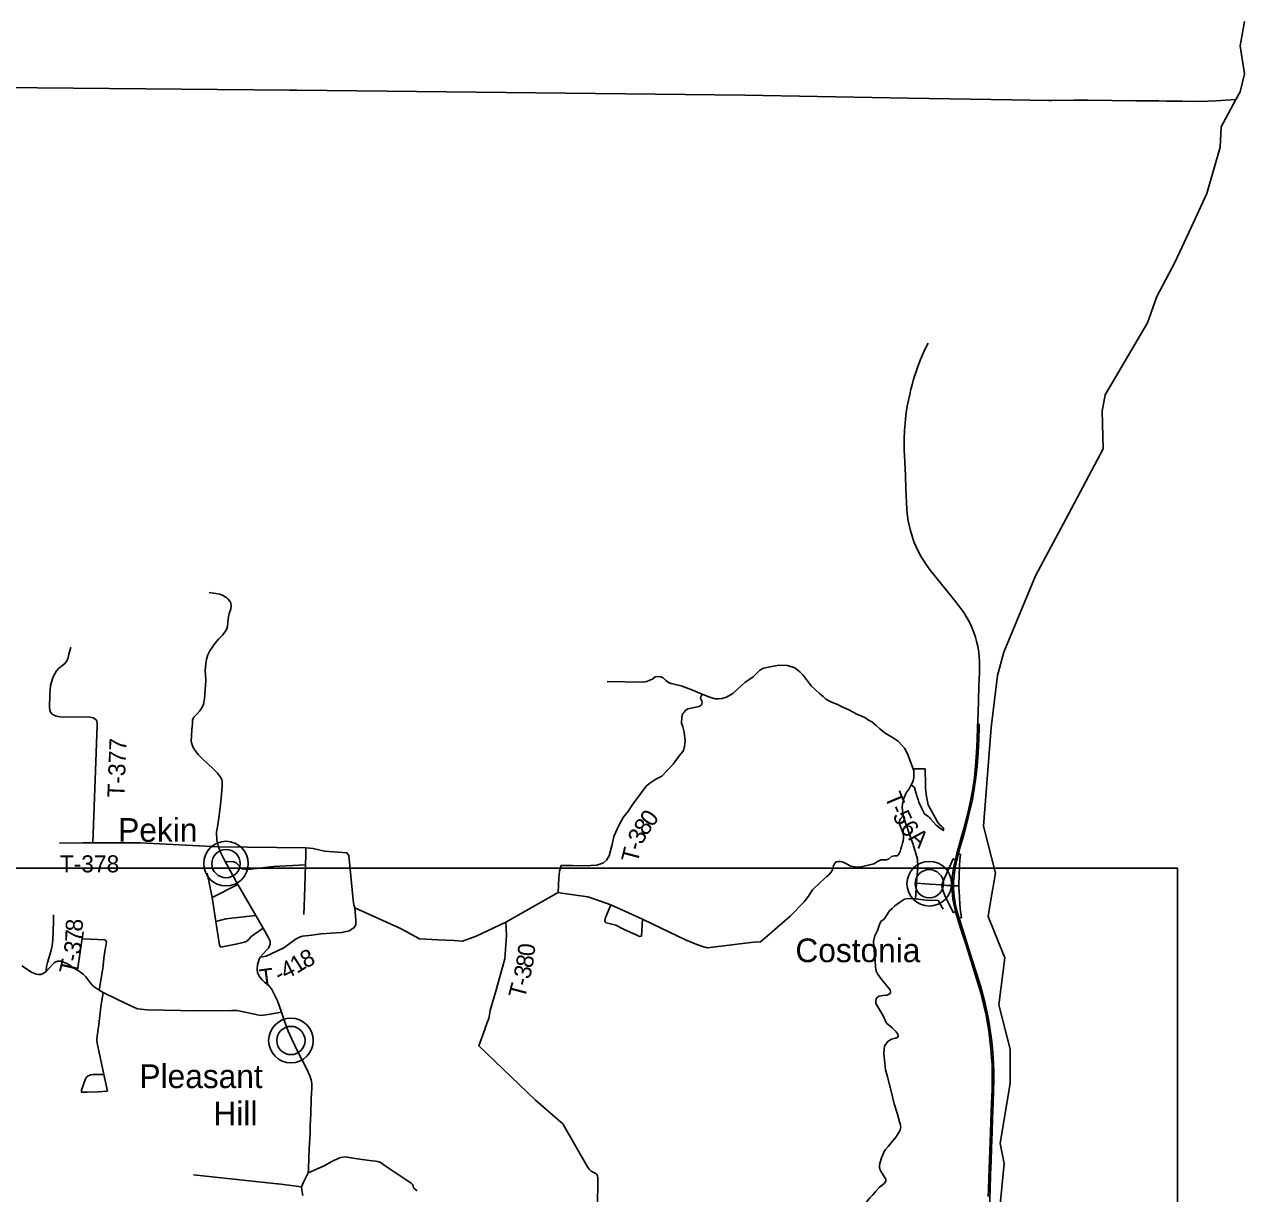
# Model space of a CAD drawing. Extents: x 2402298 to 2498138, y 789485 to 950881.
# Drawn here: x 2476534 to 2498020, y 883995 to 904591 of the extents above; entities that cross this region are included whole.
import ezdxf

# ---------------------------------------------------------------- set-up
doc = ezdxf.new("R2010")
doc.units = 0
for name, color, linetype in [('GM_X_County', 7, 'Continuous'), ('GM_X_County_Road', 7, 'Continuous'), ('GM_X_Interchange_Ramps', 7, 'Continuous'), ('GM_X_State_Route', 7, 'Continuous'), ('GM_X_Township', 7, 'Continuous'), ('GM_X_Township_Road', 7, 'Continuous'), ('GM_X_Township_Road_Text', 7, 'Continuous'), ('GM_X_Unincorporated', 7, 'Continuous'), ('GM_X_Unincorporated_Text', 7, 'Continuous'), ('SH_Text', 7, 'Continuous')]:
    doc.layers.add(name, color=color, linetype=linetype)

msp = doc.modelspace()

# ---------------------------------------------------------------- linework, layer by layer
at = {"layer": 'GM_X_County'}
msp.add_lwpolyline([(2498018, 904641), (2497940, 904212), (2498020, 903722), (2497939, 903401), (2497868, 903270), (2497606, 902788), (2497589, 902427), (2497357, 901615), (2497080, 901013), (2496789, 900399), (2496476, 899798), (2496307, 899333), (2495566, 898065), (2495514, 897781), (2495530, 897113), (2494920, 895961), (2494340, 894878), (2493781, 893531), (2493667, 893121), (2493560, 892205), (2493420, 890468), (2493631, 889637), (2493547, 889137), (2493504, 888879), (2493797, 888149), (2493690, 887319), (2493891, 886541), (2493889, 885939), (2493714, 884880), (2493786, 884527), (2493696, 883623)], dxfattribs=at)
at = {"layer": 'GM_X_County_Road'}
for points in [[(2486798, 893016), (2487422, 893005), (2487492, 893018), (2487598, 893066), (2487643, 893096), (2487687, 893104), (2487741, 893096), (2487782, 893078), (2487829, 893032), (2487874, 893001), (2487921, 892978), (2488096, 892942), (2488286, 892872), (2488469, 892792), (2488566, 892753), (2488637, 892726), (2488695, 892709), (2488753, 892712), (2488820, 892716), (2488896, 892741), (2489008, 892802), (2489222, 893001), (2489290, 893047), (2489364, 893101), (2489481, 893218), (2489551, 893252), (2489639, 893270), (2489753, 893295), (2489817, 893305), (2489972, 893297), (2490098, 893255), (2490187, 893188), (2490246, 893127), (2490386, 892942), (2490465, 892869), (2490534, 892805), (2490597, 892751), (2490648, 892707), (2490744, 892653), (2490841, 892615), (2490948, 892564), (2491065, 892510), (2491193, 892442), (2491335, 892381), (2491400, 892337), (2491455, 892306), (2491534, 892243), (2491594, 892180), (2491693, 892106), (2491831, 892023), (2491917, 891964), (2491980, 891903), (2492029, 891842), (2492085, 891742), (2492184, 891476), (2492194, 891445), (2492197, 891409), (2492197, 891399)], [(2492197, 891399), (2492197, 891366), (2492194, 891331), (2492188, 891291), (2492175, 891246), (2492150, 891193), (2492113, 891127), (2492063, 891057), (2492011, 890941), (2491994, 890858), (2491987, 890804), (2492007, 890649), (2492112, 890339), (2492185, 890144), (2492260, 889884), (2492267, 889753), (2492245, 889462), (2492472, 889446), (2492691, 889432), (2492779, 889425), (2492867, 889420), (2492896, 889418), (2492988, 889414)], [(2476487, 888005), (2476659, 887898), (2476700, 887879), (2476743, 887861), (2476780, 887854), (2476823, 887856), (2476866, 887873), (2476916, 887908), (2476977, 887974), (2477031, 888032), (2477056, 888059), (2477085, 888077), (2477120, 888087), (2477148, 888090), (2477184, 888089), (2477225, 888073), (2477282, 888046), (2477321, 888023), (2477393, 887975), (2477468, 887932), (2477519, 887896), (2477570, 887861), (2477616, 887811), (2477685, 887722), (2477747, 887647), (2477853, 887576), (2477921, 887540), (2478149, 887425), (2478294, 887355), (2478418, 887297), (2478524, 887251), (2478687, 887230), (2479584, 887214), (2480181, 887220), (2480281, 887218), (2480475, 887177), (2480586, 887154), (2480690, 887134), (2480828, 887151), (2481063, 887191)]]:
    msp.add_lwpolyline(points, dxfattribs=at)
at = {"layer": 'GM_X_Interchange_Ramps'}
for points in [[(2492988, 889414), (2492987, 889450), (2492992, 889587), (2492998, 889774), (2493008, 889870), (2493020, 889971), (2492982, 889980)], [(2492928, 889879), (2492889, 889894), (2492820, 889736), (2492737, 889554), (2492715, 889507), (2492701, 889463), (2492691, 889432)], [(2492691, 889432), (2492691, 889413), (2492695, 889387), (2492713, 889326), (2492748, 889228), (2492786, 889151), (2492824, 889076), (2492868, 888989), (2492888, 888945), (2492931, 888958)], [(2492992, 888850), (2493035, 888858), (2493020, 888968), (2493008, 889081), (2492998, 889225), (2492988, 889393), (2492988, 889414)]]:
    msp.add_lwpolyline(points, dxfattribs=at)
at = {"layer": 'GM_X_State_Route'}
for points in [[(2493506, 883946), (2493510, 884073), (2493518, 884269), (2493523, 884430), (2493529, 884590), (2493534, 884751), (2493540, 884910), (2493546, 885071), (2493553, 885271), (2493559, 885427), (2493564, 885588), (2493569, 885707), (2493573, 885827), (2493576, 885988), (2493575, 886148), (2493572, 886268), (2493565, 886388), (2493553, 886546), (2493536, 886705), (2493514, 886864), (2493488, 887024), (2493461, 887174), (2493425, 887334), (2493399, 887434), (2493374, 887529), (2493330, 887682), (2493271, 887872), (2493198, 888105), (2493114, 888369), (2493030, 888636), (2492965, 888842), (2492931, 888958), (2492915, 889026), (2492899, 889097), (2492885, 889179), (2492875, 889259), (2492867, 889354), (2492867, 889420), (2492869, 889494), (2492873, 889567), (2492882, 889647), (2492901, 889763), (2492928, 889879), (2492954, 889985), (2492987, 890110), (2493036, 890287), (2493068, 890401), (2493110, 890557), (2493157, 890749), (2493199, 890944), (2493232, 891127), (2493261, 891326), (2493283, 891525), (2493301, 891763), (2493311, 892001), (2493318, 892212), (2493326, 892454), (2493333, 892690), (2493342, 892931), (2493350, 893171), (2493351, 893281), (2493349, 893370), (2493345, 893450), (2493337, 893528), (2493320, 893640), (2493301, 893724), (2493279, 893800), (2493252, 893879), (2493211, 893983), (2493174, 894061), (2493119, 894159), (2493074, 894231), (2493006, 894326), (2492907, 894453), (2492733, 894667), (2492606, 894823), (2492481, 894980), (2492412, 895075), (2492369, 895140), (2492325, 895213), (2492272, 895313), (2492237, 895387), (2492204, 895464), (2492177, 895538), (2492152, 895616), (2492131, 895691), (2492113, 895770), (2492098, 895848), (2492086, 895928), (2492074, 896047), (2492067, 896167), (2492056, 896407), (2492046, 896647), (2492036, 896885), (2492027, 897097), (2492026, 897150), (2492027, 897287), (2492033, 897443), (2492042, 897560), (2492050, 897645), (2492063, 897756), (2492080, 897866), (2492099, 897973), (2492122, 898073), (2492143, 898164), (2492164, 898243), (2492186, 898321), (2492209, 898396), (2492234, 898472), (2492260, 898549), (2492303, 898659), (2492343, 898756), (2492396, 898876), (2492446, 898977)], [(2479952, 890575), (2479962, 890658), (2479986, 890848), (2480003, 891027), (2480016, 891181), (2480016, 891235), (2480011, 891290), (2479985, 891333), (2479933, 891401), (2479857, 891477), (2479761, 891563), (2479676, 891650), (2479592, 891730), (2479534, 891808), (2479502, 891868), (2479473, 891960), (2479479, 892060), (2479483, 892165), (2479491, 892268), (2479492, 892333), (2479520, 892388), (2479574, 892445), (2479625, 892502), (2479661, 892552), (2479688, 892619), (2479707, 892710), (2479724, 892949), (2479728, 893042), (2479721, 893130), (2479719, 893216), (2479728, 893328), (2479739, 893412), (2479764, 893486), (2479797, 893554), (2479838, 893617), (2479889, 893683), (2479953, 893761), (2480023, 893833), (2480063, 893883), (2480090, 893932), (2480108, 893985), (2480119, 894056), (2480129, 894160), (2480137, 894206), (2480167, 894299), (2480177, 894351), (2480170, 894398), (2480154, 894433), (2480119, 894471), (2480097, 894490), (2480077, 894502), (2480031, 894530), (2479969, 894553), (2479904, 894565), (2479865, 894571), (2479788, 894585)], [(2493529, 883788), (2493539, 884061), (2493548, 884331), (2493556, 884565), (2493564, 884801), (2493575, 885078), (2493583, 885319), (2493593, 885600), (2493600, 885798), (2493605, 885999), (2493603, 886152), (2493599, 886279), (2493593, 886398), (2493580, 886556), (2493563, 886715), (2493541, 886874), (2493515, 887031), (2493487, 887182), (2493452, 887345), (2493424, 887453), (2493389, 887589), (2493368, 887655), (2493298, 887880), (2493225, 888112), (2493141, 888376), (2493057, 888644), (2492992, 888850), (2492958, 888965), (2492926, 889106), (2492904, 889242), (2492896, 889353), (2492896, 889418), (2492896, 889489), (2492899, 889536), (2492910, 889654), (2492931, 889770), (2492952, 889870), (2492982, 889980), (2493020, 890119), (2493074, 890315), (2493136, 890545), (2493184, 890741), (2493227, 890940), (2493260, 891127), (2493289, 891326), (2493311, 891525), (2493329, 891763), (2493339, 892002), (2493346, 892213), (2493348, 892271)], [(2481439, 883960), (2481419, 884057), (2481415, 884113), (2481450, 884194), (2481491, 884276), (2481528, 884361), (2481538, 884427), (2481542, 884625), (2481550, 884777), (2481564, 885074), (2481568, 885189), (2481575, 885408), (2481584, 885662), (2481594, 885860), (2481594, 885934), (2481583, 886001), (2481561, 886070), (2481508, 886190), (2481351, 886494), (2481238, 886730), (2481178, 886856), (2481115, 887035), (2481063, 887191), (2480992, 887389), (2480928, 887518), (2480885, 887600), (2480828, 887671), (2480763, 887717), (2480720, 887761), (2480678, 887808), (2480655, 887849), (2480637, 887891), (2480631, 887942), (2480637, 888025), (2480665, 888122), (2480683, 888163), (2480741, 888221), (2480794, 888279), (2480839, 888326), (2480863, 888389), (2480861, 888441), (2480829, 888513), (2480736, 888671), (2480610, 888895), (2480292, 889438), (2480071, 889845), (2479987, 890008), (2479953, 890106), (2479920, 890221), (2479919, 890361), (2479942, 890493), (2479952, 890575)]]:
    msp.add_lwpolyline(points, dxfattribs=at)
at = {"layer": 'GM_X_Township'}
msp.add_lwpolyline([(2471955, 903500), (2476767, 903474), (2481204, 903434), (2481335, 903433), (2489222, 903345), (2492100, 903289), (2493922, 903261), (2494572, 903249), (2494576, 903250), (2494618, 903250), (2495010, 903254), (2495137, 903258), (2495262, 903257), (2496107, 903247), (2496512, 903242), (2496642, 903240), (2496922, 903237), (2497230, 903236), (2497515, 903245), (2497868, 903270), (2497606, 902788), (2497589, 902427), (2497357, 901615), (2497080, 901013), (2496789, 900399), (2496476, 899798), (2496307, 899333), (2495566, 898065), (2495514, 897781), (2495530, 897113), (2494920, 895961), (2494340, 894878), (2493781, 893531), (2493667, 893121), (2493560, 892205), (2493420, 890468), (2493631, 889637), (2493547, 889137), (2493504, 888879), (2493797, 888149), (2493690, 887319), (2493891, 886541), (2493889, 885939), (2493714, 884880), (2493786, 884527), (2493696, 883623)], dxfattribs=at)
at = {"layer": 'GM_X_Township_Road'}
for p, q in [((2479839, 889210), (2480292, 889438)), ((2485012, 888779), (2485930, 889301)), ((2492227, 889188), (2492245, 889462)), ((2477468, 887932), (2477548, 888452)), ((2477552, 888483), (2477958, 888464)), ((2479509, 884323), (2480982, 884169))]:
    msp.add_line(p, q, dxfattribs=at)
for points in [[(2477741, 890174), (2477767, 890972), (2477794, 891605), (2477818, 892246), (2477815, 892286), (2477807, 892317), (2477795, 892340), (2477775, 892361), (2477744, 892377), (2477692, 892385), (2477164, 892394), (2477128, 892400), (2477081, 892409), (2477051, 892421), (2477018, 892446), (2476995, 892477), (2476982, 892514), (2476977, 892563), (2476984, 892784), (2476996, 892944), (2477005, 892986), (2477043, 893100), (2477067, 893153), (2477101, 893202), (2477141, 893249), (2477206, 893296), (2477251, 893340), (2477279, 893378), (2477305, 893433), (2477318, 893500), (2477349, 893623)], [(2488125, 891781), (2488141, 891801), (2488160, 891876), (2488168, 891970), (2488152, 892126), (2488129, 892219), (2488102, 892285), (2488110, 892387), (2488115, 892420), (2488128, 892450), (2488148, 892471), (2488172, 892506), (2488215, 892535), (2488414, 892574), (2488449, 892599), (2488465, 892621), (2488470, 892644), (2488463, 892669), (2488450, 892700), (2488440, 892722), (2488442, 892746), (2488469, 892792)], [(2485930, 889301), (2485947, 889560), (2485959, 889674), (2485971, 889738), (2485985, 889777), (2486187, 889775), (2486381, 889771), (2486509, 889772), (2486616, 889780), (2486731, 889822), (2486785, 889870), (2486828, 889943), (2486881, 890144), (2486912, 890287), (2486993, 890467), (2487080, 890622), (2487171, 890740), (2487250, 890858), (2487401, 891063), (2487484, 891173), (2487546, 891226), (2487655, 891297), (2487757, 891350), (2487959, 891559), (2488065, 891707), (2488125, 891781)], [(2492642, 890447), (2492715, 890390), (2492720, 890413), (2492718, 890424), (2492709, 890440), (2492689, 890460), (2492657, 890483), (2492617, 890534), (2492445, 890845), (2492417, 890993), (2492398, 891136), (2492403, 891198), (2492392, 891476), (2492184, 891476)], [(2492150, 891193), (2492205, 891150), (2492232, 891062), (2492252, 890985), (2492269, 890940), (2492282, 890889), (2492333, 890788), (2492354, 890741), (2492369, 890710), (2492379, 890686), (2492400, 890672), (2492444, 890644), (2492460, 890632), (2492476, 890614), (2492490, 890598), (2492591, 890487), (2492642, 890447)], [(2491981, 890112), (2491985, 890122), (2491997, 890166), (2492007, 890208), (2492015, 890256), (2492016, 890305), (2492008, 890340), (2491986, 890402), (2491957, 890474), (2491939, 890534), (2491942, 890563), (2491958, 890598), (2492007, 890649)], [(2477152, 890170), (2477561, 890174), (2477646, 890174), (2477741, 890174), (2478163, 890175), (2478574, 890175), (2479953, 890106)], [(2479953, 890106), (2481490, 890084), (2481616, 890076), (2481819, 890030), (2482213, 889999), (2482248, 889953), (2482322, 889167), (2482335, 889080), (2482352, 889029)], [(2481457, 888913), (2481463, 889061), (2481465, 889211), (2481485, 889789), (2481490, 889949), (2481490, 890084)], [(2490283, 889161), (2490339, 889233), (2490413, 889348), (2490544, 889474), (2490613, 889535), (2490663, 889582), (2490699, 889612), (2490736, 889651), (2490762, 889699), (2490780, 889771), (2490791, 889801), (2490808, 889824), (2490835, 889840), (2490871, 889848), (2490901, 889848), (2490932, 889842), (2490964, 889827), (2491010, 889802), (2491088, 889766), (2491162, 889753), (2491211, 889748), (2491245, 889748), (2491491, 889803), (2491578, 889859), (2491618, 889872), (2491706, 889874), (2491750, 889886), (2491802, 889932), (2491847, 889945), (2491898, 889948), (2491925, 889964), (2491938, 889985), (2491954, 890024), (2491964, 890071), (2491981, 890112)], [(2480071, 889845), (2480224, 889841), (2480262, 889819), (2480361, 889718), (2480468, 889705), (2480923, 889755), (2481485, 889789)], [(2479992, 888336), (2479968, 888370), (2479903, 888791), (2479839, 889210), (2479755, 889638)], [(2485930, 889301), (2485997, 889287), (2486244, 889255), (2486455, 889224), (2486677, 889145), (2486861, 889080), (2487416, 888829), (2487597, 888741), (2488174, 888465), (2488372, 888384), (2488494, 888343), (2488524, 888335)], [(2486861, 889080), (2486758, 888841), (2486752, 888801), (2486761, 888783), (2486775, 888764), (2486829, 888753), (2486951, 888722), (2487085, 888653), (2487319, 888546), (2487363, 888523), (2487399, 888531), (2487416, 888829)], [(2488524, 888335), (2488560, 888326), (2489372, 888427), (2489495, 888431), (2489662, 888570), (2490016, 888882), (2490260, 889131), (2490283, 889161)], [(2491861, 889062), (2491943, 889126), (2491993, 889158), (2492029, 889179), (2492096, 889191), (2492227, 889188), (2492413, 889167), (2492621, 889158), (2492631, 889153), (2492655, 889106), (2492714, 889004)], [(2476916, 887908), (2476925, 887997), (2476942, 888065), (2476964, 888143), (2477004, 888282), (2477020, 888362), (2477034, 888471), (2477040, 888620), (2477044, 888786), (2477049, 888905)], [(2479903, 888791), (2480083, 888837), (2480610, 888895)], [(2480683, 888163), (2480729, 888164), (2480793, 888179), (2480993, 888272), (2481102, 888327), (2481214, 888405), (2481321, 888481), (2481376, 888511), (2481430, 888530), (2481597, 888550), (2481757, 888569), (2481930, 888580), (2482126, 888597), (2482253, 888625), (2482336, 888675), (2482369, 888731), (2482370, 888812), (2482352, 889029)], [(2482352, 889029), (2483156, 888663), (2483491, 888485), (2483817, 888466), (2484099, 888453), (2484246, 888440), (2484487, 888528), (2485012, 888779)], [(2491506, 884013), (2491527, 884037), (2491589, 884108), (2491637, 884144), (2491681, 884180), (2491698, 884200), (2491705, 884222), (2491700, 884248), (2491678, 884286), (2491641, 884345), (2491613, 884392), (2491598, 884428), (2491591, 884455), (2491588, 884491), (2491596, 884525), (2491628, 884627), (2491673, 884736), (2491697, 884772), (2491744, 884826), (2491794, 884887), (2491876, 884992), (2491944, 885090), (2491955, 885116), (2491962, 885144), (2491964, 885171), (2491962, 885192), (2491953, 885222), (2491943, 885261), (2491900, 885412), (2491852, 885578), (2491794, 885801), (2491733, 886054), (2491696, 886174), (2491677, 886353), (2491668, 886457), (2491672, 886539), (2491681, 886601), (2491744, 886679), (2491805, 886714), (2491870, 886732), (2491906, 886747), (2491918, 886773), (2491914, 886805), (2491884, 886842), (2491812, 886914), (2491715, 886999), (2491648, 887137), (2491561, 887285), (2491528, 887342), (2491524, 887380), (2491531, 887427), (2491555, 887457), (2491583, 887471), (2491653, 887487), (2491721, 887492), (2491761, 887506), (2491785, 887526), (2491786, 887549), (2491776, 887583), (2491632, 887758), (2491557, 887866), (2491537, 887902), (2491527, 887942), (2491520, 887987), (2491517, 888097), (2491497, 888279), (2491486, 888434), (2491494, 888491), (2491508, 888538), (2491555, 888632), (2491592, 888738), (2491616, 888787), (2491645, 888812), (2491669, 888826), (2491697, 888865), (2491723, 888909), (2491742, 888943), (2491767, 888976), (2491814, 889019), (2491861, 889062)], [(2480736, 888671), (2480584, 888567), (2480519, 888516), (2480483, 888471), (2480441, 888439), (2480412, 888425), (2480284, 888394), (2479992, 888336)], [(2484650, 886910), (2484679, 886990), (2484713, 887081), (2484738, 887222), (2484837, 887559), (2484995, 888130), (2485024, 888544), (2485012, 888779)], [(2477548, 888452), (2477552, 888483), (2477568, 888608)], [(2477853, 887576), (2477914, 887963), (2477938, 888191), (2477964, 888326), (2477979, 888431), (2477958, 888464)], [(2477914, 886095), (2477746, 886091), (2477704, 886088), (2477659, 886072), (2477632, 886052), (2477612, 886018), (2477540, 885817), (2477538, 885783), (2477641, 885782), (2477828, 885787), (2477997, 885800), (2477934, 886093), (2477850, 886481), (2477813, 886645), (2477810, 886703), (2477817, 886770), (2477842, 886973), (2477882, 887283), (2477921, 887540)], [(2486626, 883661), (2486624, 883739), (2486629, 884268), (2486628, 884307), (2486614, 884331), (2486593, 884347), (2486512, 884392), (2486479, 884423), (2486450, 884467), (2486015, 885223), (2485534, 885643), (2484538, 886597), (2484648, 886904), (2484650, 886910)], [(2481528, 884361), (2481814, 884486), (2481948, 884561), (2482083, 884627), (2482170, 884642), (2482216, 884638), (2482360, 884616), (2482649, 884574), (2482727, 884567), (2482775, 884554), (2482818, 884535), (2482871, 884499), (2483255, 884237), (2483318, 884196), (2483351, 884173), (2483367, 884158), (2483374, 884150), (2483381, 884130), (2483386, 884108), (2483388, 884095), (2483396, 884086), (2483448, 884045)], [(2480982, 884169), (2481004, 884166), (2481415, 884113)], [(2491156, 883542), (2491209, 883603), (2491258, 883658), (2491297, 883710), (2491334, 883769), (2491360, 883844), (2491390, 883887), (2491422, 883918), (2491466, 883968), (2491506, 884013)]]:
    msp.add_lwpolyline(points, dxfattribs=at)
at = {"layer": 'GM_X_Unincorporated'}
for centre, radius in [((2480084, 889808), 393), ((2480084, 889808), 249), ((2492468, 889454), 393), ((2492468, 889454), 249), ((2481227, 886692), 393), ((2481227, 886692), 249)]:
    msp.add_circle(centre, radius, dxfattribs=at)
at = {"layer": 'SH_Text'}
msp.add_lwpolyline([(2448187, 889729), (2496836, 889729), (2496836, 859271), (2448187, 859271)], close=True, dxfattribs=at)

# ---------------------------------------------------------------- texts
at = {"layer": 'GM_X_Township_Road_Text'}
for s, rotation, p in [('T-377', 87.755, (2478293, 890966)), ('T', 292.8424, (2491676, 890990)), ('-', 293.2861, (2491764, 890780)), ('8', 54.3177, (2487484, 890283)), ('0', 55.3505, (2487595, 890438)), ('5', 294.8358, (2491816, 890659)), ('3', 64.7174, (2487413, 890128)), ('6', 309.0889, (2491937, 890422)), ('A', 318.4443, (2492090, 890240)), ('-', 73.8637, (2487383, 890022)), ('T-378', 0, (2477157, 889654)), ('T', 75.811, (2487329, 889807)), ('8', 88.0149, (2477558, 888608)), ('3', 80.2124, (2477515, 888197)), ('7', 87.8139, (2477551, 888422)), ('8', 25.7086, (2481480, 887957)), ('0', 84.7164, (2485514, 888167)), ('T', 77.1955, (2477435, 887841)), ('-', 77.5076, (2477485, 888062)), ('4', 25.9343, (2481133, 887764)), ('1', 32.3771, (2481332, 887863)), ('3', 77.0167, (2485433, 887761)), ('8', 79.7101, (2485477, 887956)), ('T', 7.6252, (2480696, 887644)), ('-', 27.5351, (2481026, 887708)), ('T', 75.1914, (2485342, 887415)), ('-', 75.6099, (2485400, 887634))]:
    msp.add_text(s, height=300, rotation=rotation, dxfattribs=at).set_placement(p)
at = {"layer": 'GM_X_Unincorporated_Text'}
for s, p in [('Pekin', (2478186, 890192)), ('Costonia', (2490110, 888072)), ('Pleasant', (2478560, 885854)), ('Hill', (2479863, 885198))]:
    msp.add_text(s, height=417, rotation=0, dxfattribs=at).set_placement(p)

doc.saveas('drawing.dxf')
